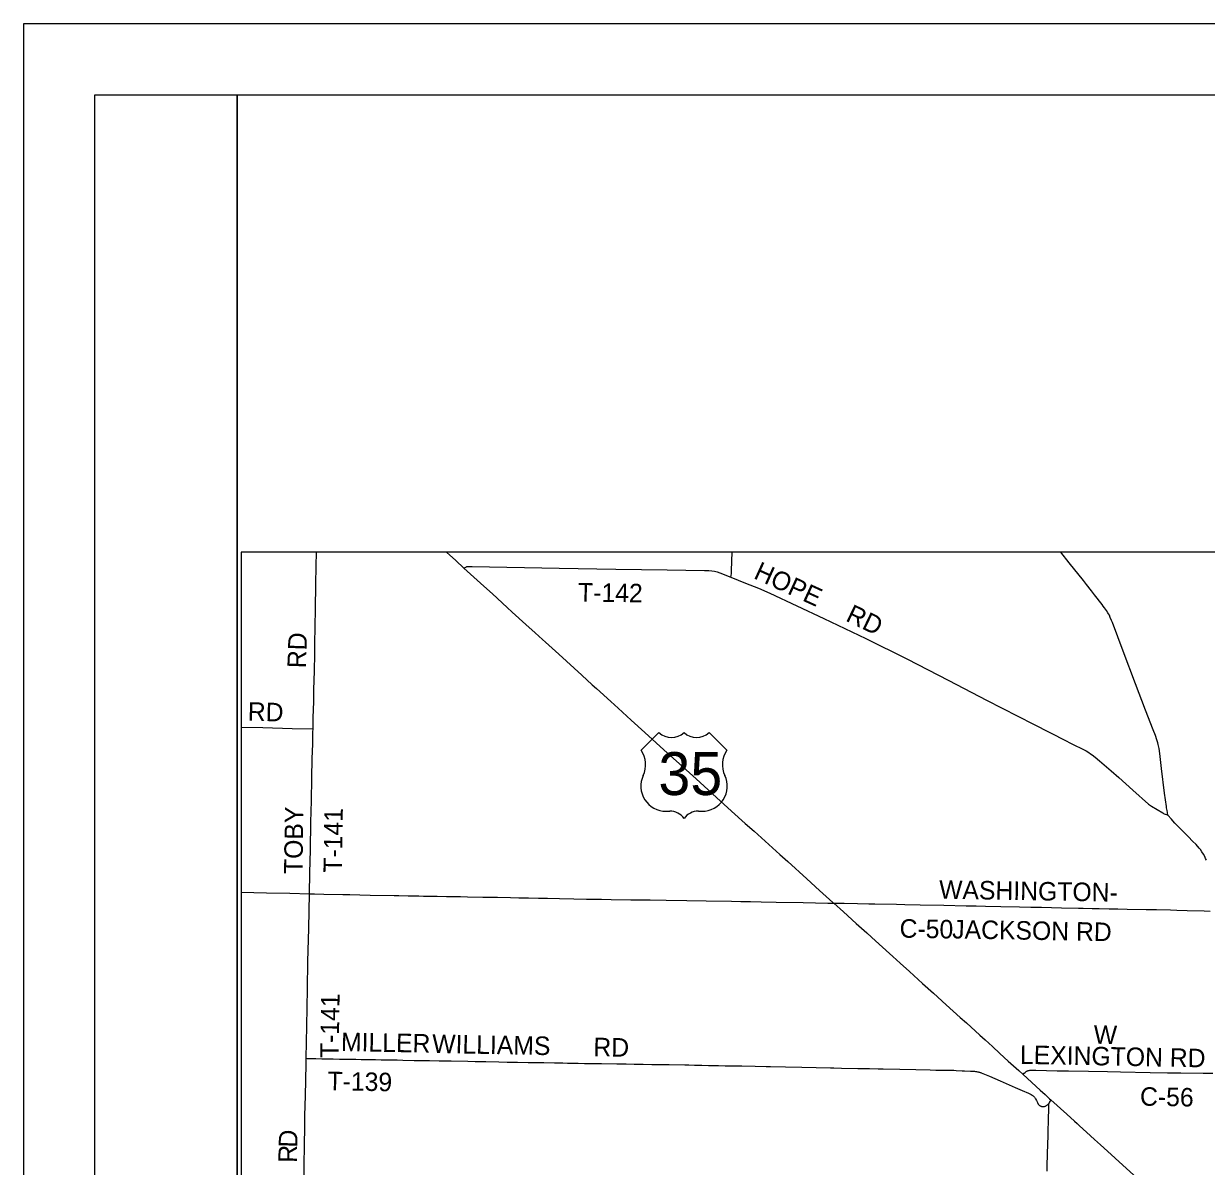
# Model space of a CAD drawing. Extents: x 1341221 to 1914484, y 79347 to 658398.
# Drawn here: x 1341221 to 1378615, y 622283 to 658398 of the extents above; entities that cross this region are included whole.
import ezdxf

# ---------------------------------------------------------------- set-up
doc = ezdxf.new("R2010")
doc.units = 0
for name, color, linetype in [('GM_X_Major_Lake', 7, 'Continuous'), ('GM_X_Major_Lake_Text', 7, 'Continuous'), ('GM_X_Major_River_Text', 7, 'Continuous'), ('GM_X_Minor_Lake_Text', 7, 'Continuous'), ('GM_X_Minor_River_Text', 7, 'Continuous'), ('GM_X_State_Shield', 7, 'Continuous'), ('GM_X_Township_Text', 7, 'Continuous'), ('GM_X_Unincorporated', 7, 'Continuous'), ('GM_X_Unincorporated_Text', 7, 'Continuous'), ('GM_X_US_Shield', 7, 'Continuous')]:
    doc.layers.add(name, color=color, linetype=linetype)

msp = doc.modelspace()

# ---------------------------------------------------------------- linework, layer by layer
at = {"layer": 'GM_X_Minor_Lake_Text'}
for points in [[(1343471, 656148), (1347971, 656148), (1347971, 561648), (1343471, 561648)], [(1347971, 656148), (1491971, 656148), (1491971, 561648), (1347971, 561648)], [(1435650, 641695), (1348099, 641695), (1348099, 580425), (1435650, 580425)]]:
    msp.add_lwpolyline(points, close=True, dxfattribs=at)
at = {"layer": 'GM_X_Minor_River_Text'}
msp.add_lwpolyline([(1341221, 559398), (1494221, 559398), (1494221, 658398), (1341221, 658398)], close=True, dxfattribs=at)
at = {"layer": 'GM_X_State_Shield'}
msp.add_lwpolyline([(1373583, 622133), (1373584, 622196), (1373586, 622363), (1373592, 622600), (1373597, 622741), (1373600, 622916), (1373604, 623056), (1373609, 623174), (1373614, 623347), (1373625, 623774), (1373632, 624099), (1373634, 624190), (1373636, 624273)], dxfattribs=at)
at = {"layer": 'GM_X_Township_Text'}
msp.add_line((1370576, 625318), (1370626, 625317), dxfattribs=at)
for points in [[(1350258, 630899), (1350273, 631554), (1350286, 632288), (1350305, 633164), (1350318, 633830), (1350331, 634553), (1350342, 635173), (1350360, 635627), (1350369, 636002), (1350370, 636110), (1350379, 636462), (1350391, 636976), (1350400, 637347), (1350412, 637942), (1350423, 638474), (1350429, 638793), (1350435, 639347), (1350444, 639892), (1350456, 640685), (1350467, 641249), (1350475, 641695)], [(1363584, 640905), (1363591, 640955), (1363599, 641018), (1363604, 641114), (1363618, 641695)], [(1355140, 641193), (1355176, 641210), (1355219, 641231), (1355236, 641236), (1355256, 641240), (1355303, 641243), (1355399, 641244), (1358149, 641190), (1359940, 641160), (1361564, 641135), (1362747, 641118), (1362815, 641115), (1362881, 641111), (1362977, 641103), (1363059, 641090), (1363147, 641071), (1363232, 641044), (1363584, 640905), (1364048, 640716), (1364455, 640554), (1364811, 640394), (1366521, 639596), (1367183, 639286), (1367849, 638964), (1369143, 638318), (1370474, 637634), (1371662, 637021), (1373148, 636259), (1374178, 635732), (1374298, 635671)], [(1348099, 636166), (1348782, 636148), (1349714, 636124), (1350370, 636110)], [(1374298, 635671), (1374811, 635411), (1374895, 635363), (1374954, 635325), (1375006, 635288), (1375101, 635213), (1375239, 635099), (1375601, 634784), (1375847, 634570), (1376294, 634167), (1376782, 633729), (1376878, 633662), (1377065, 633556), (1377236, 633451), (1377257, 633438), (1377279, 633427), (1377309, 633416), (1377357, 633399), (1377402, 633385)], [(1348099, 630949), (1348903, 630929), (1349632, 630912), (1350258, 630899)], [(1349956, 615283), (1349968, 616145), (1349990, 617280), (1350024, 618829), (1350044, 619881), (1350068, 621073), (1350085, 622141), (1350105, 623129), (1350108, 623348), (1350116, 623891), (1350128, 624506), (1350151, 625514), (1350155, 625698), (1350177, 626717), (1350194, 627898), (1350210, 628758), (1350238, 629801), (1350245, 630358), (1350258, 630899)], [(1350258, 630899), (1350413, 630896), (1350713, 630889), (1351308, 630877), (1351538, 630871), (1351845, 630863), (1352178, 630857), (1352938, 630840), (1353079, 630839), (1353379, 630834), (1353546, 630831), (1353712, 630828), (1353865, 630824), (1353942, 630823), (1354006, 630822), (1354294, 630818), (1354594, 630812), (1354767, 630810), (1355029, 630808), (1355259, 630804), (1355739, 630795), (1356199, 630786), (1356615, 630777), (1356877, 630771), (1357178, 630767), (1357498, 630760), (1357785, 630755), (1358163, 630746), (1358617, 630738), (1359013, 630730), (1359211, 630727), (1359339, 630726), (1359493, 630724), (1359800, 630718), (1360414, 630709), (1360823, 630704), (1361034, 630702), (1361539, 630694), (1362192, 630684), (1362799, 630675), (1363605, 630661), (1363893, 630655), (1364200, 630650), (1364539, 630645), (1365018, 630635), (1365863, 630618), (1366644, 630603), (1366832, 630602)], [(1350155, 625698), (1350188, 625696), (1350455, 625687), (1350653, 625684), (1350909, 625680), (1351005, 625678), (1351209, 625675), (1351350, 625674), (1351587, 625669), (1351670, 625667), (1351727, 625666), (1351894, 625664), (1352028, 625662), (1352181, 625659), (1352341, 625656), (1352527, 625653), (1352796, 625649), (1353026, 625644), (1353211, 625642), (1353569, 625633), (1354056, 625626), (1354363, 625619), (1354734, 625612), (1355265, 625602), (1355501, 625598), (1355757, 625592), (1355834, 625591), (1356243, 625584), (1356505, 625580), (1356838, 625575), (1357171, 625568), (1357670, 625561), (1358008, 625554), (1358157, 625551), (1358265, 625549), (1358419, 625546), (1358629, 625542), (1358754, 625540), (1358953, 625537), (1359486, 625530), (1359972, 625524), (1360068, 625523), (1360267, 625519), (1360529, 625514), (1360804, 625509), (1361085, 625505), (1361463, 625498), (1361629, 625497), (1362122, 625489), (1362256, 625486), (1362429, 625481), (1362525, 625480), (1362665, 625477), (1362876, 625473), (1363186, 625467), (1363401, 625464), (1363516, 625462), (1363702, 625459), (1363766, 625458), (1363927, 625456), (1364352, 625448), (1364693, 625440), (1364834, 625438), (1365314, 625427), (1365825, 625415), (1366279, 625404), (1366733, 625394), (1366842, 625391), (1367079, 625386), (1367591, 625377), (1367961, 625371), (1368236, 625366), (1368402, 625363), (1368926, 625351), (1369433, 625340), (1369883, 625331), (1370060, 625327), (1370454, 625322), (1370576, 625318)], [(1370626, 625317), (1370708, 625311), (1370894, 625300), (1370972, 625296), (1371153, 625292), (1371227, 625291), (1371255, 625290), (1371276, 625289)], [(1371276, 625289), (1371287, 625289), (1371315, 625285), (1371346, 625280), (1371376, 625274), (1371399, 625269), (1371425, 625263), (1371446, 625257), (1371464, 625252), (1371480, 625247), (1371496, 625241), (1371598, 625198), (1371755, 625128), (1372094, 624981), (1372378, 624858), (1372572, 624773), (1372794, 624676), (1372989, 624592), (1373033, 624571), (1373078, 624549), (1373104, 624535), (1373122, 624523), (1373138, 624512), (1373149, 624503), (1373161, 624491), (1373172, 624479), (1373182, 624468), (1373193, 624452), (1373204, 624436), (1373217, 624416), (1373241, 624368), (1373275, 624296), (1373287, 624270), (1373295, 624257), (1373302, 624248), (1373309, 624239), (1373320, 624228), (1373331, 624218), (1373342, 624209), (1373353, 624202), (1373364, 624195), (1373377, 624188), (1373391, 624183), (1373402, 624179), (1373414, 624177), (1373430, 624174), (1373447, 624172), (1373464, 624173), (1373481, 624175), (1373501, 624178), (1373516, 624183), (1373528, 624187), (1373543, 624194), (1373559, 624204), (1373575, 624215), (1373591, 624227), (1373605, 624239), (1373617, 624252), (1373636, 624273), (1373651, 624292), (1373660, 624305), (1373674, 624332), (1373700, 624383)]]:
    msp.add_lwpolyline(points, dxfattribs=at)
at = {"layer": 'GM_X_Unincorporated'}
for points in [[(1354587, 641695), (1354883, 641427), (1355140, 641193), (1355772, 640616), (1356043, 640373), (1356511, 639945), (1356670, 639798), (1357102, 639408), (1357391, 639145), (1357625, 638936), (1357719, 638849), (1357822, 638753), (1358140, 638466), (1358865, 637808), (1359196, 637506), (1359332, 637381), (1359783, 636974), (1360021, 636760), (1360428, 636389), (1360858, 635997), (1361582, 635340), (1361853, 635094), (1362271, 634717), (1362480, 634528), (1362737, 634298), (1363131, 633942), (1363606, 633513), (1364038, 633123), (1364314, 632875), (1365126, 632142), (1365380, 631916), (1365985, 631365), (1366389, 631001), (1366807, 630624), (1366832, 630602)], [(1366832, 630602), (1367141, 630325), (1367545, 629961), (1367876, 629660), (1368023, 629526), (1368270, 629304), (1368698, 628919), (1368930, 628708), (1369229, 628437), (1369642, 628065), (1369988, 627751), (1370388, 627392), (1370834, 626989), (1371030, 626814), (1371457, 626426), (1371618, 626281), (1371854, 626066), (1372086, 625854), (1372354, 625608), (1372521, 625458), (1372684, 625309), (1372821, 625185), (1373364, 624693), (1373520, 624549), (1373557, 624515), (1373661, 624419), (1373700, 624383)], [(1373700, 624383), (1374205, 623934), (1374443, 623715), (1374529, 623638), (1374536, 623632)], [(1374536, 623632), (1374606, 623567), (1374830, 623364), (1375083, 623133), (1375272, 622961)], [(1375272, 622961), (1375606, 622657), (1375860, 622427), (1376428, 621913), (1376547, 621807), (1376608, 621750)]]:
    msp.add_lwpolyline(points, dxfattribs=at)
at = {"layer": 'GM_X_Unincorporated_Text'}
for p, q in [((1361309, 635996), (1360743, 635431)), ((1363458, 635431), (1362892, 635996)), ((1361535, 633508), (1361648, 633508)), ((1362553, 633508), (1362666, 633508))]:
    msp.add_line(p, q, dxfattribs=at)
for centre, radius, start, end in [((1361704, 636400), 566, 225.573, 314.427), ((1362496, 636400), 566, 225.573, 314.427), ((1360094, 634977), 792, 334.5471, 35.0009), ((1364106, 634977), 792, 144.9991, 205.4529), ((1361526, 634300), 792, 154.8319, 270.6383), ((1362675, 634300), 792, 269.3617, 25.1681), ((1361648, 632942), 566, 36.8699, 90), ((1362553, 632942), 566, 90, 143.1301)]:
    msp.add_arc(centre, radius, start, end, dxfattribs=at)
at = {"layer": 'GM_X_US_Shield'}
for points in [[(1377094, 635615), (1377081, 635667), (1377051, 635765), (1377004, 635898), (1376935, 636077), (1376695, 636704), (1376379, 637535), (1375990, 638564), (1375645, 639473), (1375621, 639533), (1375579, 639633), (1375550, 639698), (1375526, 639743), (1375502, 639782), (1375460, 639847), (1375395, 639935), (1375353, 639991), (1375317, 640036), (1375080, 640346), (1374986, 640467), (1374825, 640675), (1374727, 640801), (1374283, 641362), (1374010, 641695)], [(1378619, 631956), (1378591, 632016), (1378563, 632074), (1378524, 632147), (1378477, 632225), (1378428, 632293), (1378388, 632343), (1378290, 632453), (1378182, 632562), (1378051, 632694), (1377908, 632840), (1377732, 633017), (1377621, 633131), (1377553, 633207), (1377514, 633251), (1377402, 633385), (1377389, 633467), (1377375, 633534), (1377368, 633570), (1377359, 633611), (1377352, 633651), (1377296, 634082), (1377202, 634856), (1377144, 635333), (1377122, 635485), (1377105, 635573), (1377094, 635615)], [(1366832, 630602), (1366904, 630601), (1367159, 630597), (1367581, 630590), (1367939, 630582), (1368131, 630580), (1368821, 630565), (1369083, 630560), (1369563, 630552), (1370318, 630538), (1371021, 630521), (1371335, 630517), (1371635, 630509), (1372121, 630497), (1372703, 630484), (1373061, 630476), (1373406, 630469), (1374033, 630455), (1374570, 630444), (1374724, 630441), (1375005, 630434), (1375229, 630429), (1375542, 630424), (1375817, 630418), (1376111, 630412), (1376712, 630403), (1377039, 630397), (1377479, 630387), (1377684, 630382), (1378010, 630372), (1378546, 630356), (1378739, 630350)], [(1372821, 625185), (1372860, 625227), (1372883, 625252), (1372896, 625264), (1372907, 625273), (1372922, 625283), (1372936, 625290), (1372954, 625298), (1372966, 625303), (1372984, 625309), (1372998, 625312), (1373015, 625315), (1373031, 625317), (1373054, 625319), (1373083, 625319), (1373127, 625320), (1373160, 625320), (1373224, 625319), (1373903, 625306), (1374254, 625299), (1374894, 625286), (1375489, 625276), (1375905, 625269), (1376840, 625252), (1377383, 625242), (1377805, 625235), (1378516, 625226), (1378816, 625224)]]:
    msp.add_lwpolyline(points, dxfattribs=at)

# ---------------------------------------------------------------- texts
at = {"layer": 'GM_X_Major_Lake'}
for s in ['0', '/']:
    msp.add_text(s, height=1.95, dxfattribs=at).set_placement((1362100, 634685))
msp.add_text('35', height=1.95, rotation=0, dxfattribs=at).set_placement((1361697, 634281))
at = {"layer": 'GM_X_Major_Lake_Text'}
for s, rotation, p in [('WASHINGTON-', 359.0324, (1370161, 630742)), ('C-50', 358.9714, (1368912, 629513)), ('JACKSON RD', 358.9931, (1370577, 629487)), ('W', 358.5506, (1375046, 626160)), ('LEXINGTON RD', 358.8875, (1372717, 625523)), ('C-56', 358.9714, (1376514, 624202))]:
    msp.add_text(s, height=585, rotation=rotation, dxfattribs=at).set_placement(p)
at = {"layer": 'GM_X_Major_River_Text'}
for s, rotation, p in [('HOPE', 335.4517, (1364272, 640880)), ('T-142', 359.1569, (1358748, 640136)), ('RD', 334.3105, (1367182, 639537)), ('RD', 88.0252, (1350142, 638019)), ('RD', 358.5175, (1348301, 636370)), ('TOBY', 89.2428, (1350038, 631519)), ('T-141', 89.1574, (1351284, 631561)), ('T-141', 89.1574, (1351181, 625701)), ('MILLER', 358.8918, (1351251, 625928)), ('WILLIAMS', 358.901, (1354134, 625868)), ('RD', 359.0109, (1359230, 625765)), ('T-139', 358.8762, (1350823, 624692)), ('D', 88.2813, (1349867, 622869)), ('R', 88.9735, (1349858, 622391))]:
    msp.add_text(s, height=585, rotation=rotation, dxfattribs=at).set_placement(p)
at = {"layer": 'GM_X_Unincorporated_Text'}
msp.add_text('35', height=1357.4, dxfattribs=at).set_placement((1361291, 634017))

doc.saveas('drawing.dxf')
